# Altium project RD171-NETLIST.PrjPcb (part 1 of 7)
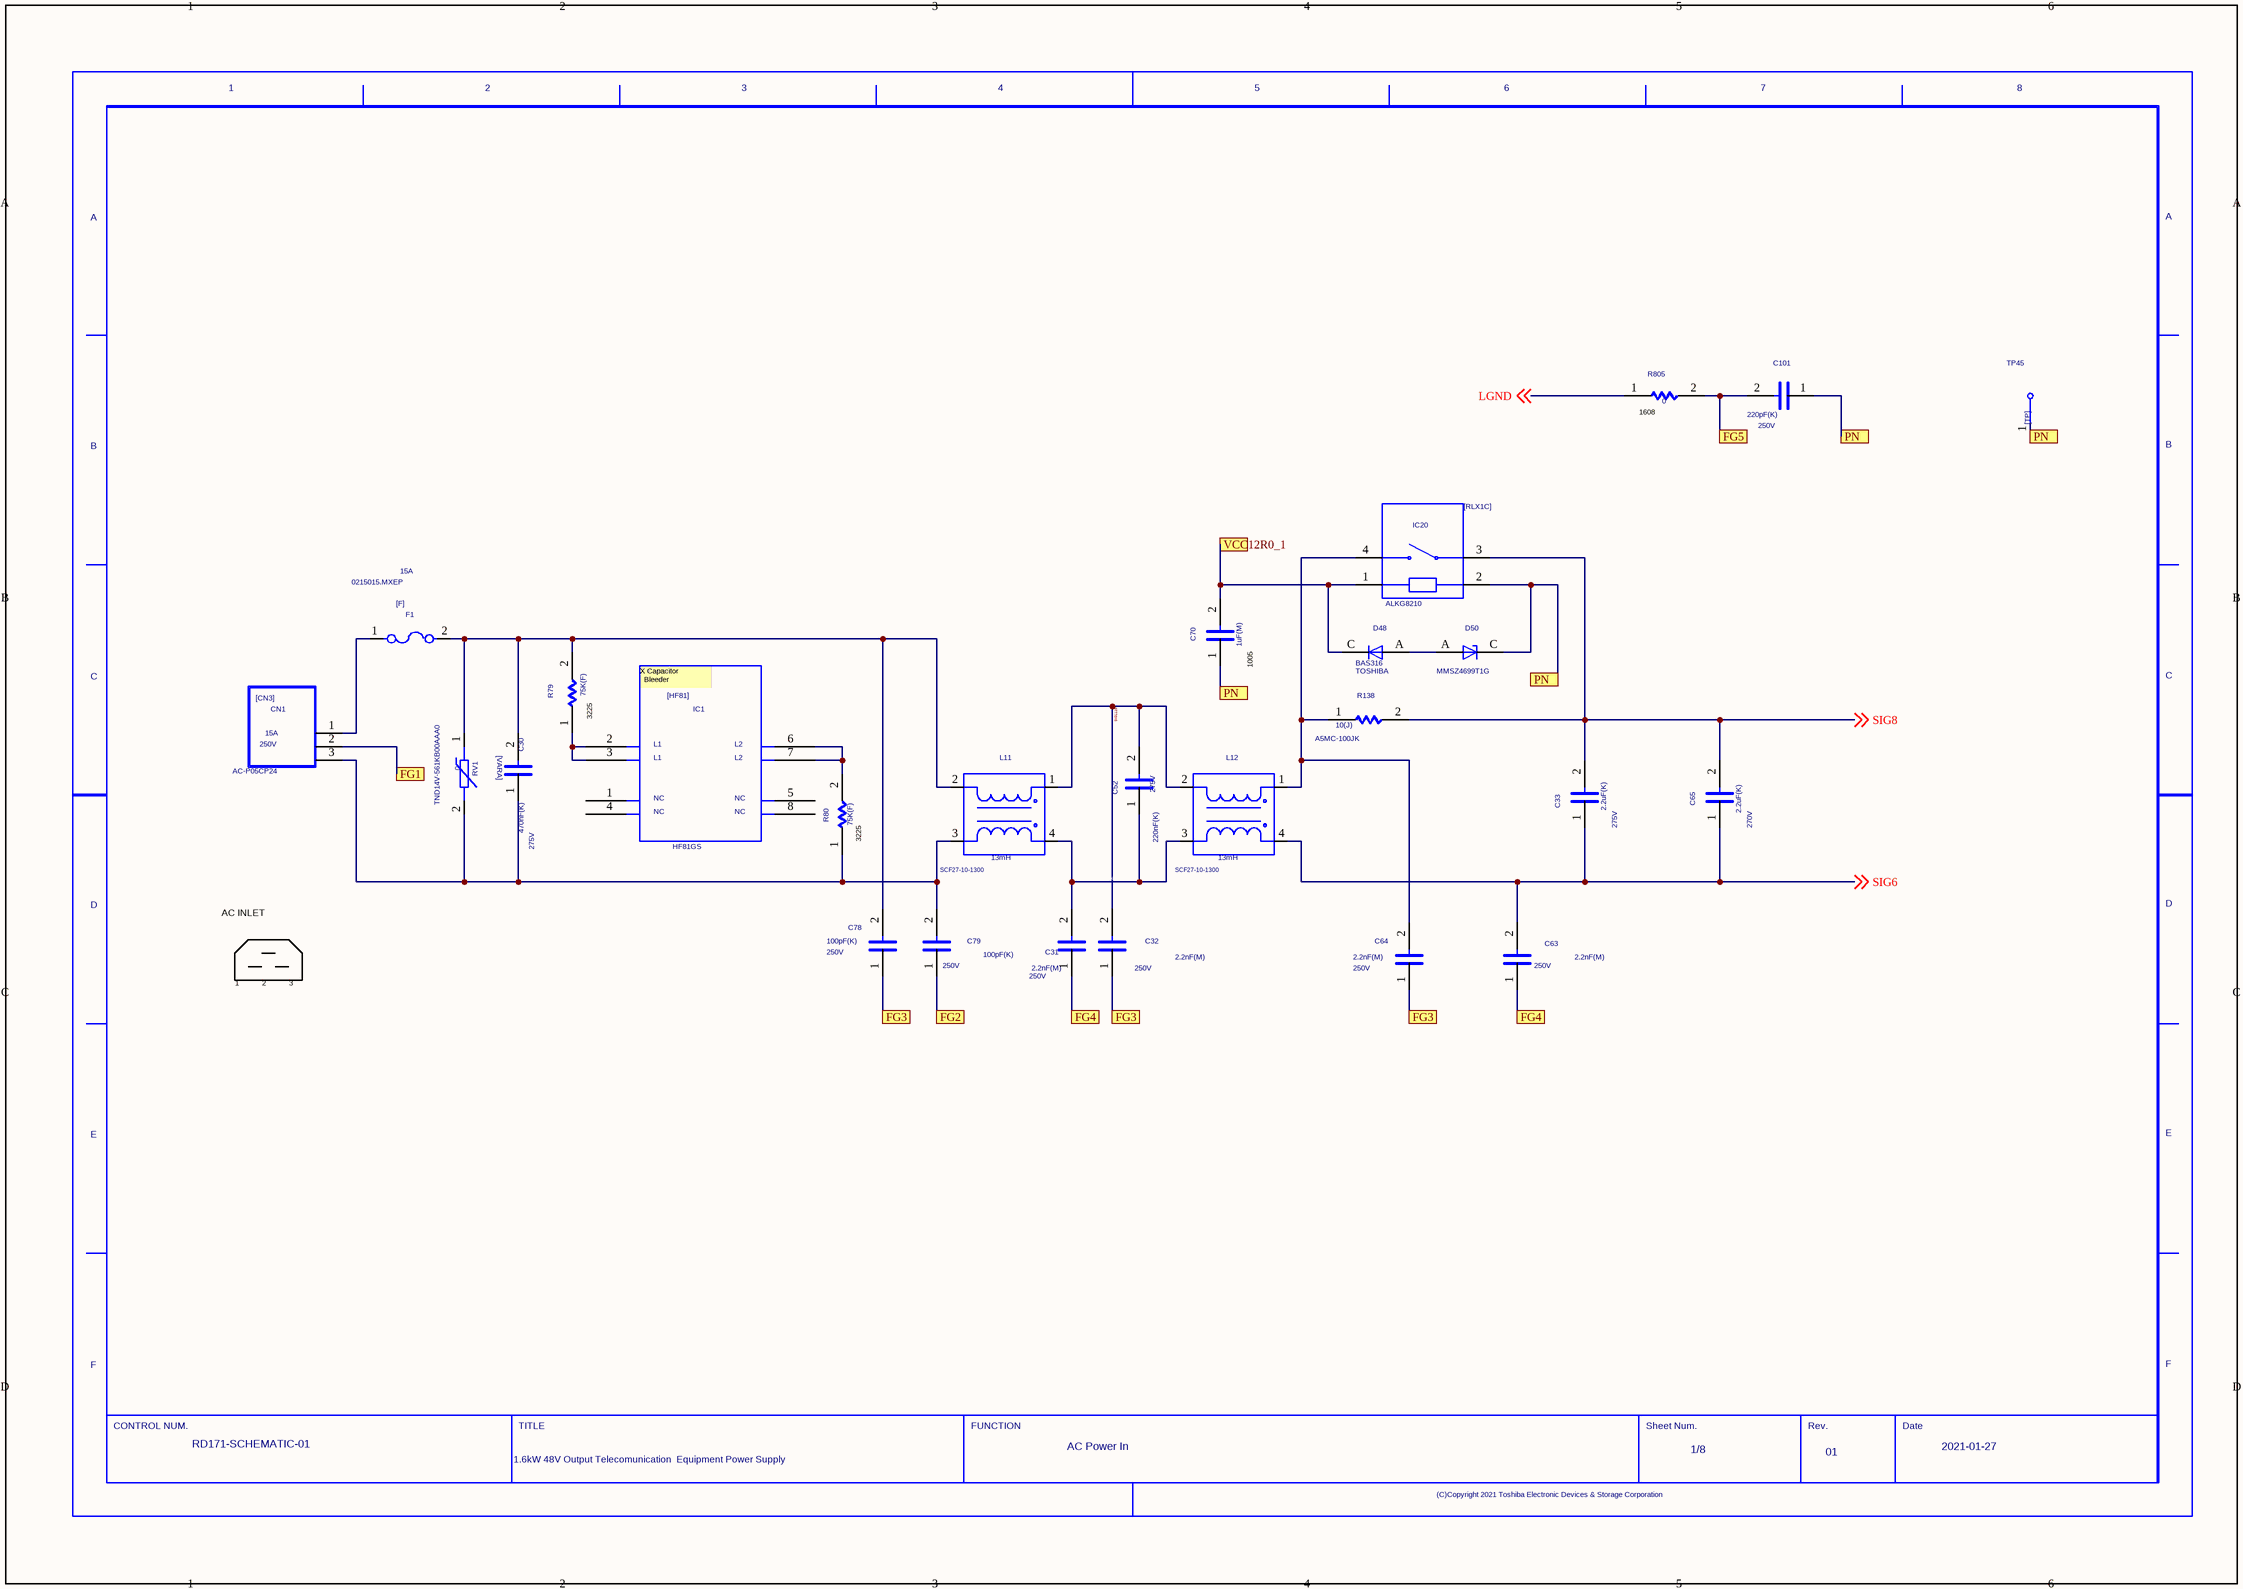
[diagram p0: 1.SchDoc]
8 sheets, 474 parts. Net scope: flat (ports and power ports of the same name join across sheets).
Sheets:
  1.SchDoc
  2.SchDoc
  3.SchDoc
  4.SchDoc
  5.SchDoc
  6.SchDoc
  7.SchDoc
  8.SchDoc

## Sheet 1.SchDoc
size 420 x 297 mm

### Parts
(Parts that share a designator on the sheet are numbered #1, #2 ... from top to bottom, then left to right.)
C30  VAL2: 275V  VAL1: 470nF(K)  [LE474-M]  (hidden comment: 470nF)
C31  VAL2: 250V  VAL1: 2.2nF(M)  [DE2E3KY222MN3AM02F]  (hidden comment: 2.2nF)
C32  VAL2: 250V  VAL1: 2.2nF(M)  [DE2E3KY222MN3AM02F]  (hidden comment: 2.2nF)
C33  VAL2: 275V  VAL1: 2.2uF(K)  [890324026034CS]  (hidden comment: 2.2uF)
C52  VAL2: 275V  VAL1: 220nF(K)  [LE224-M]  (hidden comment: 220nF)
C63  VAL2: 250V  VAL1: 2.2nF(M)  [DE2E3KY222MN3AM02F]  (hidden comment: 2.2nF)
C64  VAL2: 250V  VAL1: 2.2nF(M)  [DE2E3KY222MN3AM02F]  (hidden comment: 2.2nF)
C65  VAL2: 270V  VAL1: 2.2uF(K)  [890324026034CS]  (hidden comment: 2.2uF)
C70  VAL1: 1uF(M)  (hidden comment: 1uF)
C78  VAL2: 250V  VAL1: 100pF(K)  [DE2B3KY101KA3BM02F]  (hidden comment: 100pF)
C79  VAL2: 250V  VAL1: 100pF(K)  [DE2B3KY101KA3BM02F]  (hidden comment: 100pF)
C101  VAL2: 250V  VAL1: 220pF(K)  [DE2B3KY221KA3BM02F]  (hidden comment: 220pF)
CN1  VAL2: 250V  [AC-P05CP24]  (hidden comment: 15A)
D48  USERCOMPTEXT3: TOSHIBA  [BAS316]  (hidden comment: D48)
D50  D50  [MMSZ4699T1G]  (value not drawn)
F1  VAL1: 15A  [0215015.MXEP]  (hidden comment: 15 A)
IC1  IC1  [HF81GS]  (value not drawn)
IC20  IC20  [ALKG8210]  (value not drawn)
L11  13mH  [SCF27-10-1300]
L12  13mH  [SCF27-10-1300]
R79  VAL1: 75K(F)  (hidden comment: 75k)
R80  VAL1: 75K(F)  (hidden comment: 75k)
R138  VAL1: 10(J)  [A5MC-100JK]  (hidden comment: 10_2.1W- FUSE)
R805  0
RV1  560V  [TND14V-561KB00AAA0]  (value not drawn)
TP45  TP45  [LC-22-S-WHITE]  (value not drawn)
U?#1  DATE: 2021-01-27  REVISION: 01  SHEETNUMBER: 1/8  FUNCTION: AC Power In  TITLE: 1.6kW 48V Output Telecomunication / Equipment Power Supply  DRAWINGNUMBER: RD171-SCHEMATIC-01  (hidden comment: WAKU_DEF100)

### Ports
FG1, FG2, FG3, FG4, FG5, PN, VCC12R0_1

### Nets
LGND: R805.1 ; off-sheet LGND
SIG1: C30.2 C78.2 F1.2 L11.2 R79.2 RV1.1
SIG2: C30.1 C79.2 CN1.3 L11.3 R80.1 RV1.2
SIG6: C33.1 C63.2 C65.1 L12.4 ; off-sheet SIG6
SIG8: C33.2 C65.2 IC20.3 R138.2 ; off-sheet SIG8
SIG9: IC1.2 IC1.3 R79.1
SIG10: IC1.6 IC1.7 R80.2
SIG193: CN1.1 F1.1
SIG200: C31.2 C52.1 L11.4 L12.3
SIG1119: C32.2 C52.2 L11.1 L12.2
SIGN275: D48.A D50.A
SIGN364: C64.2 IC20.4 L12.1 R138.1
NetC1_1: C70.1 C101.1 D50.C IC20.2 TP45.1 ; port PN
NetC31_1: C31.1 C63.1 ; port FG4
NetC32_1: C32.1 C64.1 C78.1 ; port FG3
NetC70_2: C70.2 D48.C IC20.1 ; port VCC12R0_1
NetC79_1: C79.1 ; port FG2
NetC101_2: C101.2 R805.2 ; port FG5
NetCN1_2: CN1.2 ; port FG1

Not connected (* = marked no-connect by the designer): IC1 1 4 5 8

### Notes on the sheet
- (near R805) 1608
- (near C70) 1005
- (near R79) 3225
- (near R80) 3225
- AC INLET
- 1
- 2
- 3

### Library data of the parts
C30 = C: PARTNAME: LE474-M_OK; ORIGINALSYMBOLORIGIN: (0,0); TIME: 16:40:04; UPDATEUSER: t5459927; SAVECOUNT: 1; COMPONENTNAME: C_C.Normal_package; SIZECODESMD: 3225; RATEDVOLTAGE: 100; ADSMODELNAME: s_GRM32MR72A474KA01L; CAPACITANCETOLE: K; NOMINALCAPACITA: 470n; MAKER: OKAYA; COMP: PRT_19; INSTANCENAME: INS121
C31 = C: PARTNAME: DE2E3KY222MN3AM02F_MU; ORIGINALSYMBOLORIGIN: (0,0); TIME: 16:40:04; UPDATEUSER: t5459927; SAVECOUNT: 1; QUADMODEL: CON_2.2N; FUNCTION: C_C.Normal_package; NOMINALCAPACITA: 2.2n; RATEDVOLTAGE: 250; CDMASTERCADCELG: DC0284; MAKER: MURATA; TEMPCHARACTERI2: E; SIZECODESMD: DIP; OUMEMAKER: NAE パナソニックエレクトロニックデバイス; COMP: PRT_13; ADSMODELNAME: s_ECKNTS222ME; PMPRODUCTSTYPEG: ES; FNLEADFREETHET1GT2GMCTH1: N_N_N; CAPACITANCETOLE: M; OUMECLASSIFICATION: セラミックコンデンサ; OUMEMAKERKATAMEI: ECKNTS222ME; CHIPSIZE: リードピッチ7.5mm品希望; INSTANCENAME: INS259
C32 = C: PARTNAME: DE2E3KY222MN3AM02F_MU; ORIGINALSYMBOLORIGIN: (0,0); TIME: 16:40:04; UPDATEUSER: t5459927; SAVECOUNT: 1; QUADMODEL: CON_2.2N; FUNCTION: C_C.Normal_package; NOMINALCAPACITA: 2.2n; RATEDVOLTAGE: 250; CDMASTERCADCELG: DC0284; MAKER: MURATA; TEMPCHARACTERI2: E; SIZECODESMD: DIP; OUMEMAKER: NAE パナソニックエレクトロニックデバイス; ADSCNVFLAG: ON; COMP: PRT_13; ADSMODELNAME: s_ECKNTS222ME; PMPRODUCTSTYPEG: ES; FNLEADFREETHET1GT2GMCTH1: N_N_N; CAPACITANCETOLE: M; OUMECLASSIFICATION: セラミックコンデンサ; OUMEMAKERKATAMEI: ECKNTS222ME; CHIPSIZE: リードピッチ7.5mm品希望; INSTANCENAME: INS269
C33 = C: PARTNAME: 890324026034CS_WE; ORIGINALSYMBOLORIGIN: (0,0); TIME: 16:40:04; UPDATEUSER: t5459927; SAVECOUNT: 1; COMPONENTNAME: C_C.Normal_package; FNLEADFREETHET1GT2GMCTH1: 9_N_N; SIZECODESMD: DIP; RATEDVOLTAGE: 250; OUMEMAKER: CHM 日本ケミコン; CAPACITANCETOLE: K; NOMINALCAPACITA: 2.2u; OUMECLASSIFICATION: フィルャRンデンサ; MAKER: Wurth; OUMEMAKERKATAMEI: TACB2E225K; CDMASTERCADCELG: DC0511; QUADMODEL: CON_2.2U; COMP: PRT_18; INSTANCENAME: INS309
C52 = C: PARTNAME: LE224-M_OK; ORIGINALSYMBOLORIGIN: (0,0); TIME: 16:40:04; UPDATEUSER: t5459927; SAVECOUNT: 1; COMPONENTNAME: C_C.Normal_package; FNLEADFREETHET1GT2GMCTH1: N_N_N; SIZECODESMD: DIP; RATEDVOLTAGE: 275; OUMEMAKER: NIS ニッセイ電機; CAPACITANCETOLE: M; NOMINALCAPACITA: 220n; OUMECLASSIFICATION: フィルャRンデンサ; MAKER: OKAYA; OUMEMAKERKATAMEI: R40KI322000**M; QUADMODEL: CON_220N; COMP: PRT_17; INSTANCENAME: INS279
C63 = C: PARTNAME: DE2E3KY222MN3AM02F_MU; ORIGINALSYMBOLORIGIN: (0,0); TIME: 16:40:04; UPDATEUSER: t5459927; SAVECOUNT: 1; QUADMODEL: CON_2.2N; FUNCTION: C_C.Normal_package; NOMINALCAPACITA: 2.2n; RATEDVOLTAGE: 250; CDMASTERCADCELG: SIK0018; MAKER: MURATA; TEMPCHARACTERI2: E; SIZECODESMD: DIP; OUMEMAKER: MRT 村田製作所; COMP: PRT_13; ADSMODELNAME: s_DE2E3KY222MN3AM02F; PMPRODUCTSTYPEG: PC1; FNLEADFREETHET1GT2GMCTH1: N_N_N; CAPACITANCETOLE: M; OUMECLASSIFICATION: セラミックコンデンサ; CHIPSIZE: リードピッチ7.5mm品希望; INSTANCENAME: INS289
C64 = C: PARTNAME: DE2E3KY222MN3AM02F_MU; ORIGINALSYMBOLORIGIN: (0,0); TIME: 16:40:04; UPDATEUSER: t5459927; SAVECOUNT: 1; QUADMODEL: CON_2.2N; FUNCTION: C_C.Normal_package; NOMINALCAPACITA: 2.2n; RATEDVOLTAGE: 250; CDMASTERCADCELG: SIK0018; MAKER: MURATA; TEMPCHARACTERI2: E; SIZECODESMD: DIP; OUMEMAKER: MRT 村田製作所; COMP: PRT_13; ADSMODELNAME: s_DE2E3KY222MN3AM02F; PMPRODUCTSTYPEG: PC1; FNLEADFREETHET1GT2GMCTH1: N_N_N; CAPACITANCETOLE: M; OUMECLASSIFICATION: セラミックコンデンサ; CHIPSIZE: リードピッチ7.5mm品希望; INSTANCENAME: INS299
C65 = C: PARTNAME: 890324026034CS_WE; ORIGINALSYMBOLORIGIN: (0,0); TIME: 16:40:04; UPDATEUSER: t5459927; SAVECOUNT: 1; COMPONENTNAME: C_C.Normal_package; FNLEADFREETHET1GT2GMCTH1: 9_N_N; SIZECODESMD: DIP; RATEDVOLTAGE: 250; OUMEMAKER: CHM 日本ケミコン; CAPACITANCETOLE: K; NOMINALCAPACITA: 2.2u; OUMECLASSIFICATION: フィルャRンデンサ; MAKER: Wurth; OUMEMAKERKATAMEI: TACB2E225K; CDMASTERCADCELG: DC0511; QUADMODEL: CON_2.2U; COMP: PRT_18; INSTANCENAME: INS319
C70 = C: PARTNAME: Chip1005_GS_2; ORIGINALSYMBOLORIGIN: (0,0); TIME: 16:40:04; UPDATEUSER: t5459927; SAVECOUNT: 1; QUADMODEL: CON_1U; FUNCTION: C_C.Normal_package; NOMINALCAPACITA: 1u; RATEDVOLTAGE: 25; CDMASTERCADCELG: KC0005; MAKER: TDK; TEMPCHARACTERI2: B; SIZECODESMD: 1005; OUMEMAKER: MRT 村田製作所; COMP: PRT_52; ADSMODELNAME: s_GRM155B31E105KA12D; PMPRODUCTSTYPEG: HD1; FNLEADFREETHET1GT2GMCTH1: 3_0_N; VAL3: C1005X5R1E105M050BC; VAL2: 25V; CAPACITANCETOLE: K; OUMECLASSIFICATION: セラミックコンデンサ; OUMEMAKERKATAMEI: GRM155B31E105KA12D; INSTANCENAME: INS339
C78 = C: PARTNAME: DE2B3KY101KA3BM02F_MU; ORIGINALSYMBOLORIGIN: (0,0); TIME: 16:40:04; UPDATEUSER: t5459927; SAVECOUNT: 1; QUADMODEL: CON_100P; FUNCTION: C_C.Normal_package; NOMINALCAPACITA: 100p; RATEDVOLTAGE: 250; CDMASTERCADCELG: RDK0051; MAKER: MURATA; TEMPCHARACTERI2: B; OUMEMAKER: MRT 村田製作所; COMP: PRT_29; ADSMODELNAME: s_DE1B3KX101KA4BL01; FNLEADFREETHET1GT2GMCTH1: N_N_N; CAPACITANCETOLE: K; OUMECLASSIFICATION: セラミックコンデンサ; OUMEMAKERKATAMEI: DE1B3KX101KA4BL01; CHIPSIZE: リードピッチ7.5mm品希望; INSTANCENAME: INS239
C79 = C: PARTNAME: DE2B3KY101KA3BM02F_MU; ORIGINALSYMBOLORIGIN: (0,0); TIME: 16:40:04; UPDATEUSER: t5459927; SAVECOUNT: 1; QUADMODEL: CON_100P; FUNCTION: C_C.Normal_package; NOMINALCAPACITA: 100p; RATEDVOLTAGE: 250; CDMASTERCADCELG: RDK0051; MAKER: MURATA; TEMPCHARACTERI2: B; OUMEMAKER: MRT 村田製作所; COMP: PRT_29; ADSMODELNAME: s_DE1B3KX101KA4BL01; FNLEADFREETHET1GT2GMCTH1: N_N_N; CAPACITANCETOLE: K; OUMECLASSIFICATION: セラミックコンデンサ; OUMEMAKERKATAMEI: DE1B3KX101KA4BL01; CHIPSIZE: リードピッチ7.5mm品希望; INSTANCENAME: INS249
C101 = C: PARTNAME: DE2B3KY221KA3BM02F_MU; ORIGINALSYMBOLORIGIN: (0,0); TIME: 16:40:04; UPDATEUSER: t5459927; SAVECOUNT: 1; QUADMODEL: CON_220P; FUNCTION: C_C.Normal_package; NOMINALCAPACITA: 220p; RATEDVOLTAGE: 1K; CDMASTERCADCELG: RD0002; MAKER: MURATA; TEMPCHARACTERI2: B; SIZECODESMD: DIP; OUMEMAKER: MRT 村田製作所; COMP: PRT_50; ADSMODELNAME: s_DEBB33A221KC1B; FNLEADFREETHET1GT2GMCTH1: 9_1_N; CAPACITANCETOLE: K; OUMECLASSIFICATION: セラミックコンデンサ; OUMEMAKERKATAMEI: DEBB33A221KC1B; INSTANCENAME: INS329
CN1 = CN3: PARTNAME: AC-P05CP24_ED; ORIGINALSYMBOLORIGIN: (0,0); TIME: 16:40:05; UPDATEUSER: t5459927; SAVECOUNT: 1; COMP: PRT_61; FUNCTION: CN3_CN3.Normal_package; MAKER: ECHO ELECTRIC; INSTANCENAME: INS363
D48 = D: PARTNAME: BAS316_TS_B; UPDATEUSER: t5459927; UPDATETIME: 16:40:05; SAVECOUNT: 1; SAVEAREA0: -225,-91,12804,7836; ORIGINALSYMBOLORIGIN: (0,0); FUNCTION: D_D.Normal_package; CDMASTERCADCELG: D8101D; FORWARDVOLTAGEM: 0; OUMEMAKER: IFO インフィニオンテクノロジーズ; MOUNTINGFORMSMD: SMD; COMP: PRT_26; ADSMODELNAME: s_BAS16_02W; FNLEADFREETHET1GT2GMCTH1: N_N_N; OUMECLASSIFICATION: その他ダイオード; OUMEMAKERKATAMEI: BAS16-02W; INSTANCENAME: INS163
D50 = ZD: PARTNAME: MMSZ4***T*G_OS_A; OUMEPARTTYPE: D; UPDATEUSER: t5459927; UPDATETIME: 16:40:05; SAVECOUNT: 1; SAVEAREA0: -4630,-153,17114,13055; ORIGINALSYMBOLORIGIN: (0,0); FUNCTION: ZD_ZD.Normal_package; CDMASTERCADCELG: MMK0127; MAKER: ON Semiconductor; FORWARDVOLTAGEM: 0; OUMEMAKER: ONS オンセミコンダクター; MOUNTINGFORMSMD: SMD; COMP: PRT_47; ADSMODELNAME: s_MMSZ4681T1G; FNLEADFREETHET1GT2GMCTH1: N_N_N; ZENERVOLTAGEMAX: 2.52; ZENERVOLTAGEMIN: 2.28; OUMECLASSIFICATION: 定電圧ダイオード; OUMEMAKERKATAMEI: MMSZ4681T1G; INSTANCENAME: INS153
F1 = F: PARTNAME: 02150***XEP_LF; ORIGINALSYMBOLORIGIN: (0,0); TIME: 16:40:04; UPDATEUSER: t5459927; SAVECOUNT: 1; COMP: PRT_21; RATEDINTERRUPTI: 0; FUNCTION: F_F.Normal_package; MOUNTINGFORMSMD: SMD; MAKER: Littelfuse; INSTANCENAME: INS109
IC1 = L81: PARTNAME: HF81GS_MPS; UPDATEUSER: t5459927; UPDATETIME: 16:40:04; SAVECOUNT: 1; SAVEAREA0: -25132,-33687,51942,1841; ORIGINALSYMBOLORIGIN: (0,0); COMP: PRT_45; FUNCTION: L81_L81.Normal_package; MAKER: MPS; INSTANCENAME: INS131
IC20 = RLX1C: PARTNAME: ALKG*2**_PN; SAVEAREA0: -15461,-296,40419,28727; ORIGINALSYMBOLORIGIN: (0,0); SAVECOUNT: 1; TIME: 14:49:55; UPDATEUSER: cae; UPDATETIME: 11:13:08; COMP: PRT_1; FUNCTION: RLX1C_RLX1C.Normal_package; MAKER: PANASONIC; INSTANCENAME: INS349
L11 = HM_DLWHN6702: PARTNAME: SCF27-10-1300_TN; UPDATEUSER: t5459927; UPDATETIME: 16:40:05; DEVICENAME: DLW21HN670SQ2; SAVECOUNT: 1; SAVEAREA0: -21350,-26515,41553,39372; ORIGINALSYMBOLORIGIN: (0,0); VAL2: 10A; COMPONENTNAME: HM-DLWHN6702_HM-DLWHN6702.Normal_package; MAKER: NEC TOKIN; COMP: PRT_22; INSTANCENAME: INS175
L12 = HM_DLWHN6702: PARTNAME: SCF27-10-1300_TN; UPDATEUSER: t5459927; UPDATETIME: 16:40:05; DEVICENAME: DLW21HN670SQ2; SAVECOUNT: 1; SAVEAREA0: -21350,-26515,41553,39372; ORIGINALSYMBOLORIGIN: (0,0); VAL2: 10A; COMPONENTNAME: HM-DLWHN6702_HM-DLWHN6702.Normal_package; MAKER: NEC TOKIN; COMP: PRT_22; INSTANCENAME: INS191
R79 = R: PARTNAME: Chip3225_GS_1; ORIGINALSYMBOLORIGIN: (0,0); TIME: 16:40:04; UPDATEUSER: t5459927; SAVECOUNT: 1; QUADMODEL: RES_56K; FUNCTION: R_R.Normal_package; CDMASTERCADCELG: DR903A; MAKER: PANASONIC; RESISTANCETOLER: F; SIZECODESMD: 3225; OUMEMAKER: KOA コーア; POWERRATING: 250m; MOUNTINGFORMSMD: SMD; NOMINALRESISTAN: 56K; COMP: PRT_23; ADSMODELNAME: s_RK73H2ETE563F; FNLEADFREETHET1GT2GMCTH1: N_N_N; VAL3: ERJ-14NF7502U; VAL2: 500mW,±1%; OUMECLASSIFICATION: 表面実装用固定抵抗器; OUMEMAKERKATAMEI: RK73H2ETE563F; INSTANCENAME: INS219
R80 = R: PARTNAME: Chip3225_GS_1; ORIGINALSYMBOLORIGIN: (0,0); TIME: 16:40:04; UPDATEUSER: t5459927; SAVECOUNT: 1; QUADMODEL: RES_56K; FUNCTION: R_R.Normal_package; CDMASTERCADCELG: DR903A; MAKER: PANASONIC; RESISTANCETOLER: F; SIZECODESMD: 3225; OUMEMAKER: KOA コーア; POWERRATING: 250m; MOUNTINGFORMSMD: SMD; NOMINALRESISTAN: 56K; COMP: PRT_23; ADSMODELNAME: s_RK73H2ETE563F; FNLEADFREETHET1GT2GMCTH1: N_N_N; VAL3: ERJ-14NF7502U; VAL2: 500mW,±1%; OUMECLASSIFICATION: 表面実装用固定抵抗器; OUMEMAKERKATAMEI: RK73H2ETE563F; INSTANCENAME: INS229
R138 = R: PARTNAME: A5MC_UC; ORIGINALSYMBOLORIGIN: (0,0); TIME: 16:40:04; UPDATEUSER: t5459927; SAVECOUNT: 1; COMP: PRT_33; CHIPSIZE: 13x9xH25.5; FUNCTION: R_R.Normal_package; MAKER: TAKMAN; INSTANCENAME: INS207
R805 = R: PARTNAME: Chip1608_GS_1; ORIGINALSYMBOLORIGIN: (0,0); TIME: 16:40:04; UPDATEUSER: t5459927; SAVECOUNT: 1; QUADMODEL: RES_0; FUNCTION: R_R.Normal_package; CDMASTERCADCELG: KCK0203; MAKER: KOA; RESISTANCETOLER: X; SIZECODESMD: 1608; OUMEMAKER: KOA コーア; POWERRATING: 100m; MOUNTINGFORMSMD: SMD; COMP: PRT_8; ADSMODELNAME: s_RK73Z1JTTD; PMPRODUCTSTYPEG: DME-HD1-PC1; FNLEADFREETHET1GT2GMCTH1: 3_2_N; VAL3: RK73Z1JTTD; VAL2: 100mW; OUMECLASSIFICATION: 表面実装用固定抵抗器; INSTANCENAME: INS17025352
RV1 = VARA: PARTNAME: TND14V-561_CC; OUMEPARTTYPE: RV; UPDATEUSER: t5459927; UPDATETIME: 16:40:05; SAVECOUNT: 1; SAVEAREA0: -9950,-8554,25168,13619; ORIGINALSYMBOLORIGIN: (0,0); FUNCTION: VARA_VARA.Normal_package; RATEDVOLTAGE: 0; CDMASTERCADCELG: KC0008; MAKER: NIPPON CHEMICON; OUMEMAKER: TDK ＴＤＫ; MOUNTINGFORMSMD: SMD; COMP: PRT_37; FNLEADFREETHET1GT2GMCTH1: N_N_N; OUMECLASSIFICATION: バリスタ; OUMEMAKERKATAMEI: AVR-M1608C220KT6AB; INSTANCENAME: INS99
TP45 = TP: PARTNAME: LC-22_GS; UPDATEUSER: t5459927; UPDATETIME: 16:40:05; SAVECOUNT: 1; SAVEAREA0: -242,-92,12810,7836; ORIGINALSYMBOLORIGIN: (0,0); COMP: PRT_49; FUNCTION: TP_TP.Normal_package; MAKER: MAC8; INSTANCENAME: INS379
U?#1 = WAKU_DEF100: PLOTTIME: HH:MM; SAVEAREA0: 168739,-66042,466246,90057; TIME: 14:30:25; UPDATEUSER: t5459927; UPDATETIME: 15:16:57; SAVECOUNT: 5; OriginalSymbolOrigin: (10160,284480)

## Sheet 2.SchDoc
size 431 x 292 mm
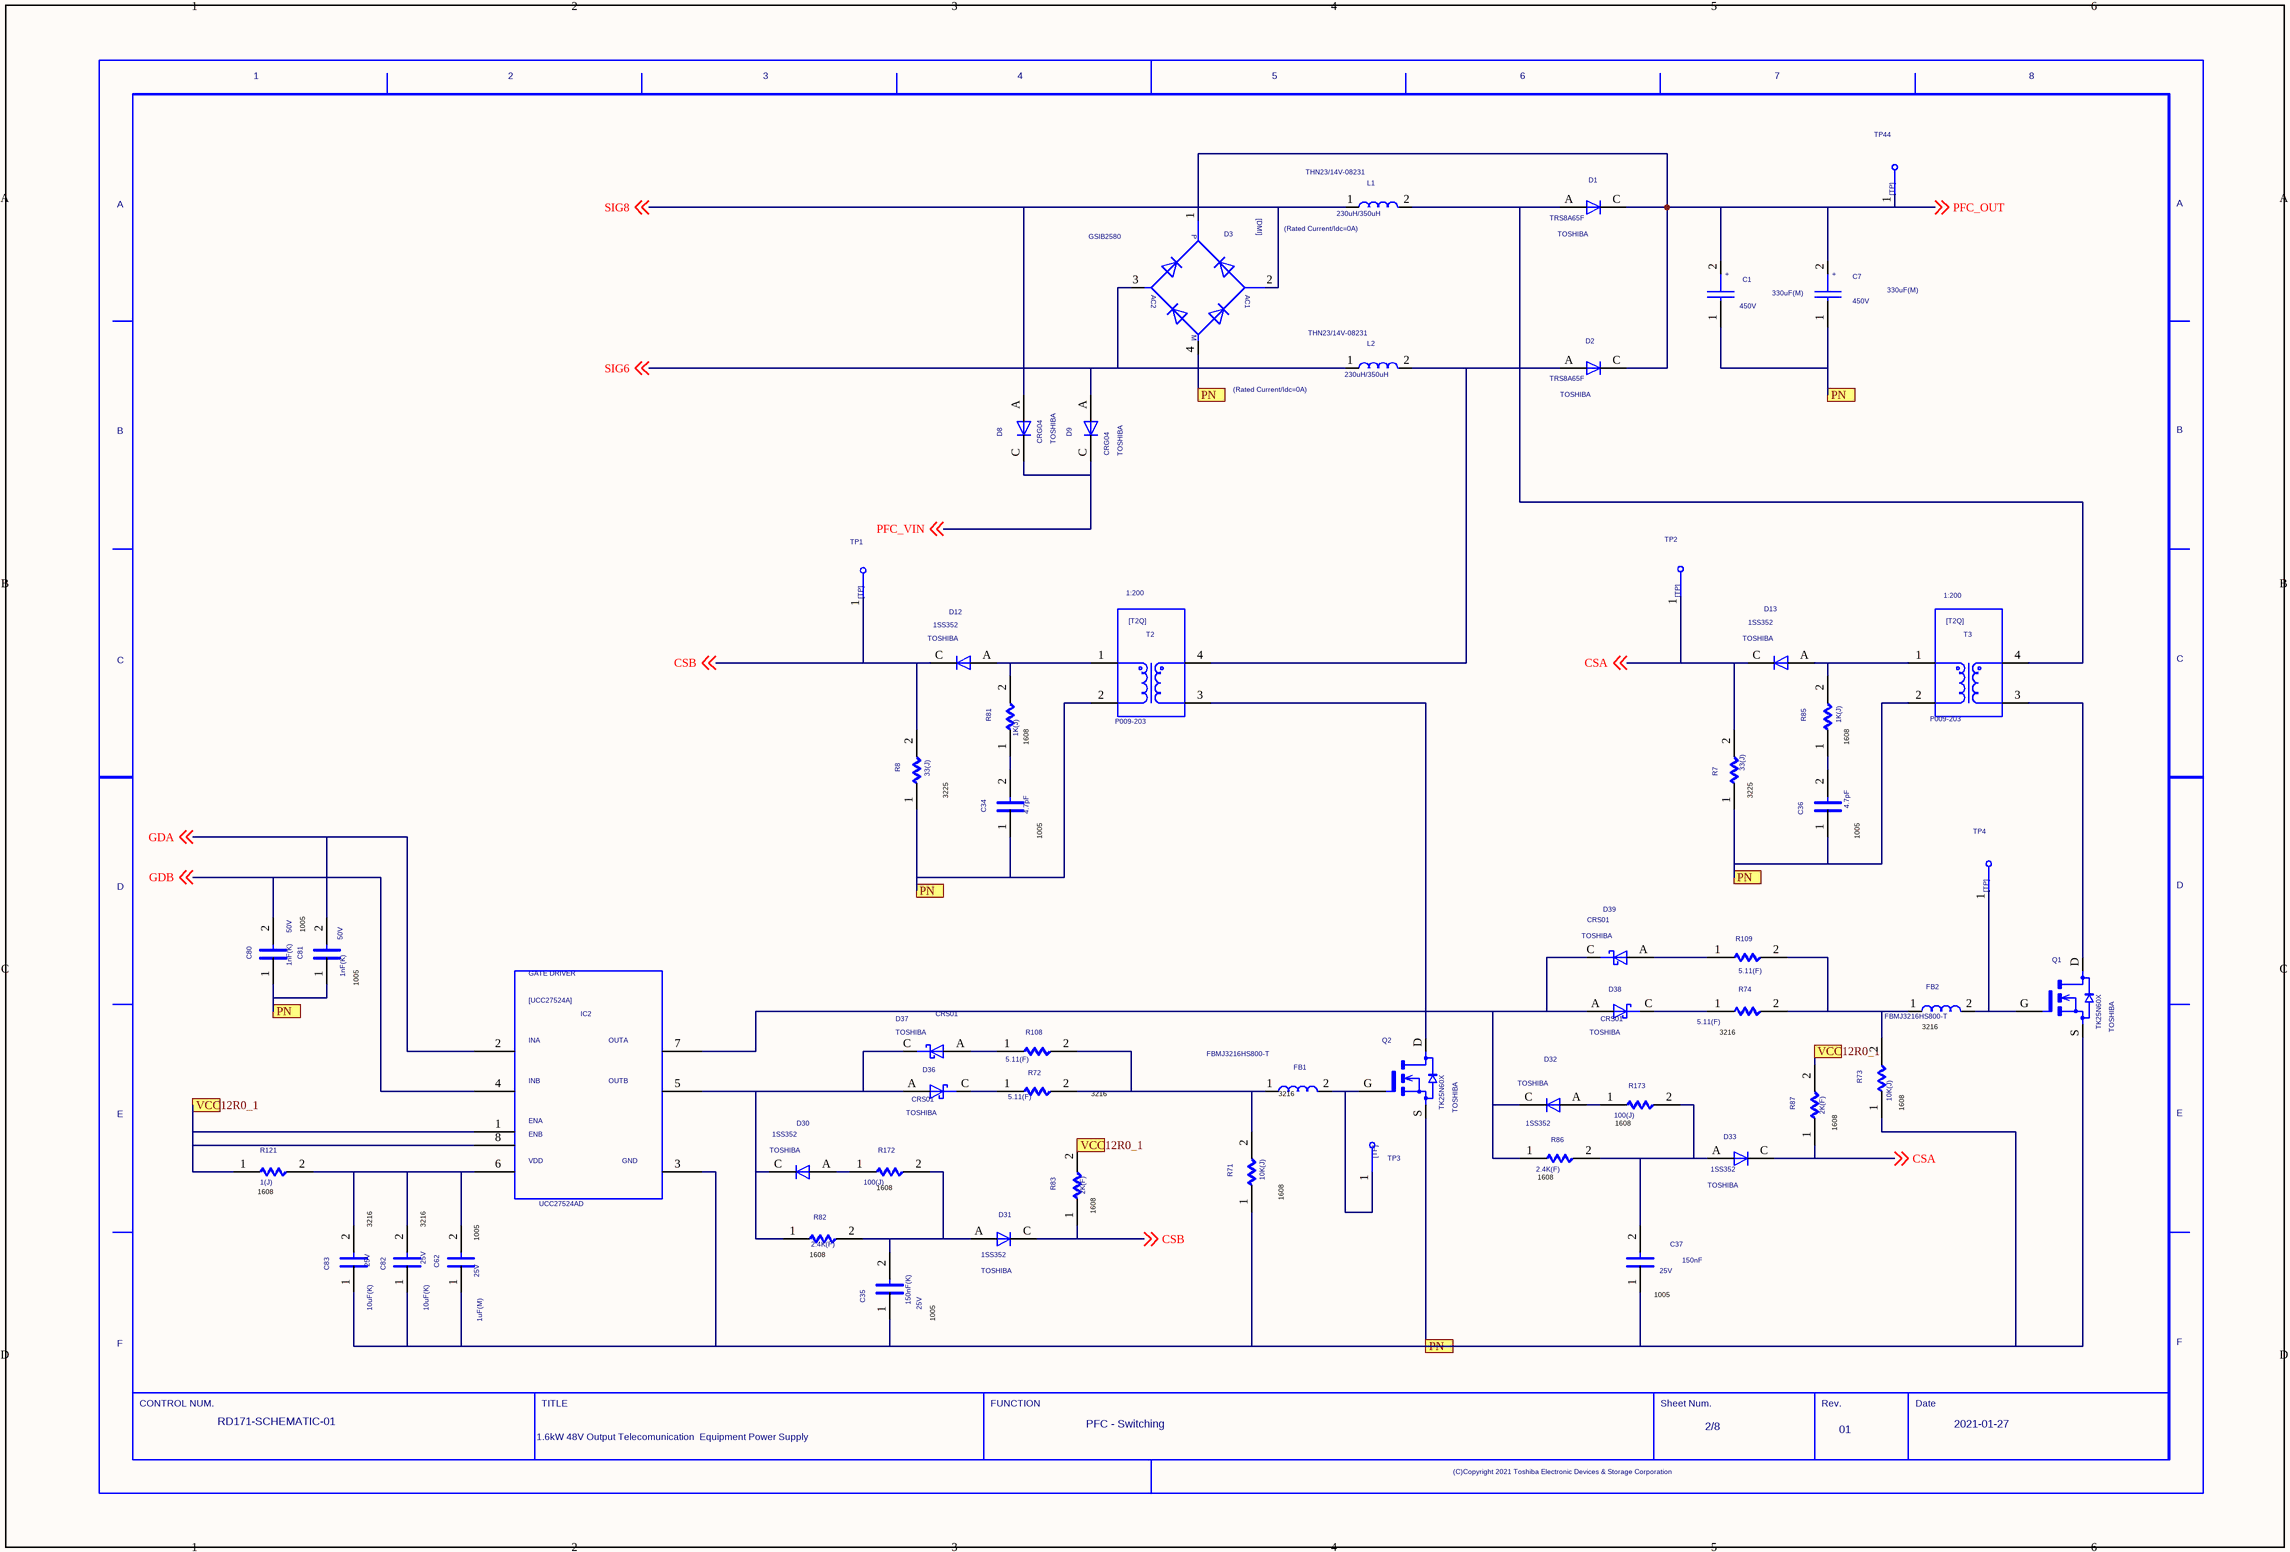
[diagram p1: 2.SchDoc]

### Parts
(Parts that share a designator on the sheet are numbered #1, #2 ... from top to bottom, then left to right.)
C1  VAL2: 450V  VAL1: 330uF(M)  [450MXK330MEFCSN30X30]  (hidden comment: 330uF)
C7  VAL2: 450V  VAL1: 330uF(M)  [450MXK330MEFCSN30X30]  (hidden comment: 330uF)
C34  4.7pF
C35  VAL2: 25V  VAL1: 150nF(K)  [C1005X5R1E154K050BC]  (hidden comment: 150nF)
C36  4.7pF
C37  VAL2: 25V  [C1005X5R1E154K050BC]  (hidden comment: 150nF)
C62  VAL2: 25V  VAL1: 1uF(M)  (hidden comment: 1uF)
C80  VAL2: 50V  VAL1: 1nF(K)  (hidden comment: 1nF)
C81  VAL2: 50V  VAL1: 1nF(K)  (hidden comment: 1nF)
C82  VAL2: 25V  VAL1: 10uF(K)  (hidden comment: 10uF)
C83  VAL2: 25V  VAL1: 10uF(K)  (hidden comment: 10uF)
D1  USERCOMPTEXT3: TOSHIBA  VAL3: TRS8A65F  [TRS8E65F]  (hidden comment: D1)
D2  USERCOMPTEXT3: TOSHIBA  VAL3: TRS8A65F  [TRS8E65F]  (hidden comment: D2)
D3  D3  [GSIB2580]  (value not drawn)
D8  USERCOMPTEXT3: TOSHIBA  [CRG04]  (hidden comment: D8)
D9  USERCOMPTEXT3: TOSHIBA  [CRG04]  (hidden comment: D9)
D12  USERCOMPTEXT3: TOSHIBA  [1SS352]  (hidden comment: D12)
D13  USERCOMPTEXT3: TOSHIBA  [1SS352]  (hidden comment: D13)
D30  USERCOMPTEXT3: TOSHIBA  [1SS352]  (hidden comment: D30)
D31  USERCOMPTEXT3: TOSHIBA  [1SS352]  (hidden comment: D31)
D32  USERCOMPTEXT3: TOSHIBA  [1SS352]  (hidden comment: D32)
D33  USERCOMPTEXT3: TOSHIBA  [1SS352]  (hidden comment: D33)
D36  USERCOMPTEXT3: TOSHIBA  [CRS01]  (hidden comment: D36)
D37  USERCOMPTEXT3: TOSHIBA  [CRS01]  (hidden comment: D37)
D38  USERCOMPTEXT3: TOSHIBA  [CRS01]  (hidden comment: D38)
D39  USERCOMPTEXT3: TOSHIBA  [CRS01]  (hidden comment: D39)
FB1  FB1  [FBMJ3216HS800-T]  (value not drawn)
FB2  FB2  [FBMJ3216HS800-T]  (value not drawn)
IC2  IC2  [UCC27524AD]  (value not drawn)
L1  VAL2: (Rated Current/Idc=0A)  VAL1: 230uH/350uH  [THN23/14V-08231]  (hidden comment: 230uH/350uH(RatedCurrent/Idc=0))
L2  VAL2: (Rated Current/Idc=0A)  VAL1: 230uH/350uH  [THN23/14V-08231]  (hidden comment: 230uH/350uH (Rated Current/Idc=0))
Q1  USERCOMPTEXT3: TOSHIBA  [TK25N60X]  (hidden comment: Q1)
Q2  USERCOMPTEXT3: TOSHIBA  [TK25N60X]  (hidden comment: Q2)
R7  VAL1: 33(J)  (hidden comment: 33)
R8  VAL1: 33(J)  (hidden comment: 33)
R71  VAL1: 10K(J)  (hidden comment: 10k)
R72  VAL1: 5.11(F)  (hidden comment: 5.11)
R73  VAL1: 10K(J)  (hidden comment: 10k)
R74  VAL1: 5.11(F)  (hidden comment: 5.11)
R81  VAL1: 1K(J)  (hidden comment: 1K)
R82  VAL1: 2.4K(F)  (hidden comment: 2.4k)
R83  VAL1: 2K(F)  (hidden comment: 2k)
R85  VAL1: 1K(J)  (hidden comment: 1K)
R86  VAL1: 2.4K(F)  (hidden comment: 2.4k)
R87  VAL1: 2K(F)  (hidden comment: 2k)
R108  VAL1: 5.11(F)  (hidden comment: 5.11)
R109  VAL1: 5.11(F)  (hidden comment: 5.11)
R121  VAL1: 1(J)  (hidden comment: 1)
R172  VAL1: 100(J)  (hidden comment: 100)
R173  VAL1: 100(J)  (hidden comment: 100)
T2  1:200  [P009-203]
T3  1:200  [P009-203]
TP1  TP1  [HK-2-S]  (value not drawn)
TP2  TP2  [HK-2-S]  (value not drawn)
TP3  TP3  [HK-2-S]  (value not drawn)
TP4  TP4  [HK-2-S]  (value not drawn)
TP44  TP44  [HK-2-S]  (value not drawn)
U?#2  DATE: 2021-01-27  REVISION: 01  SHEETNUMBER: 2/8  FUNCTION: PFC - Switching  TITLE: 1.6kW 48V Output Telecomunication / Equipment Power Supply  DRAWINGNUMBER: RD171-SCHEMATIC-01  (hidden comment: WAKU_DEF100)

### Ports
PN, VCC12R0_1

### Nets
CSA: D13.C D33.C R7.2 R87.1 TP2.1 ; off-sheet CSA
CSB: D12.C D31.C R8.2 R83.1 TP1.1 ; off-sheet CSB
GDA: C81.2 IC2.2 ; off-sheet GDA
GDB: C80.2 IC2.4 ; off-sheet GDB
PFC_OUT: C1.2 C7.2 D1.C D2.C D3.1 TP44.1 ; off-sheet PFC_OUT
PFC_VIN: D8.C D9.C ; off-sheet PFC_VIN
SIG6: D3.3 D9.A L2.1 ; off-sheet SIG6
SIG8: D3.2 D8.A L1.1 ; off-sheet SIG8
SIG11: D2.A L2.2 T2.4
SIG12: D1.A L1.2 T3.4
SIG15: D12.A R81.2 T2.1
SIG18: Q2.D T2.3
SIG20: D13.A R85.2 T3.1
SIG21: C36.2 R85.1
SIG22: Q1.D T3.3
SIG23: FB1.1 R71.2 R72.2 R108.2
SIG24: C35.2 D31.A R82.2 R172.2
SIG25: C37.2 D33.A R86.2 R173.2
SIG27: FB2.1 R73.2 R74.2 R109.2
SIG30: D32.C D38.A D39.C IC2.7 R86.1
SIG100: D36.C R72.1
SIG101: D37.A R108.1
SIG102: D30.C D36.A D37.C IC2.5 R82.1
SIG104: C62.2 C82.2 C83.2 IC2.6 R121.2
SIG105: D39.A R109.1
SIG106: D38.C R74.1
SIG1116: C34.2 R81.1
SIGN254: D30.A R172.1
SIGN255: D32.A R173.1
SIGN266: FB1.2 Q2.G TP3.1
SIGN267: FB2.2 Q1.G TP4.1
NetC1_1: C1.1 C7.1 C34.1 C35.1 C36.1 C37.1 C62.1 C80.1 C81.1 C82.1 C83.1 D3.4 IC2.3 Q1.S Q2.S R7.1 R8.1 R71.1 R73.1 T2.2 T3.2 ; port PN
NetC70_2: IC2.1 IC2.8 R83.2 R87.2 R121.1 ; port VCC12R0_1

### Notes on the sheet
- (near R81) 1608
- (near R85) 1608
- (near R8) 3225
- (near C34) 1005
- (near R7) 3225
- (near C36) 1005
- 1005
- (near C81) 1005
- (near R74) 3216
- (near FB2) 3216
- 3216
- (near FB1) 3216
- (near R73) 1608
- (near R173) 1608
- (near R87) 1608
- (near R121) 1608
- (near C62) 1005
- (near R172) 1608
- (near R83) 1608
- (near R71) 1608
- (near R86) 1608
- (near R82) 1608
- (near C37) 1005
- (near C35) 1005

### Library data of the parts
C1 = CP: PARTNAME: 450MXK330MEFCSN30X30_RB; OUMEPARTTYPE: C; UPDATEUSER: t5459927; UPDATETIME: 16:40:04; SAVECOUNT: 1; SAVEAREA0: -1450,-153,20294,13055; ORIGINALSYMBOLORIGIN: (0,0); QUADMODEL: CON_330U; FUNCTION: CP_CP.Normal_package; NOMINALCAPACITA: 330u; RATEDVOLTAGE: 450; CDMASTERCADCELG: DC213N; MAKER: RUBYCON; SIZECODESMD: DIP; OUMEMAKER: SIT ルビコン; COMP: PRT_4; FNLEADFREETHET1GT2GMCTH1: 9_N_N; VAL3: 450MXH330; CAPACITANCETOLE: M; OUMECLASSIFICATION: アルミ電解コンデンサ; OUMEMAKERKATAMEI: 450MXC330M35X40; CHIPSIZE: D35xL30; INSTANCENAME: INS1378
C7 = CP: PARTNAME: 450MXK330MEFCSN30X30_RB; OUMEPARTTYPE: C; UPDATEUSER: t5459927; UPDATETIME: 16:40:04; SAVECOUNT: 1; SAVEAREA0: -1450,-153,20294,13055; ORIGINALSYMBOLORIGIN: (0,0); QUADMODEL: CON_330U; FUNCTION: CP_CP.Normal_package; NOMINALCAPACITA: 330u; RATEDVOLTAGE: 450; CDMASTERCADCELG: DC213N; MAKER: RUBYCON; SIZECODESMD: DIP; OUMEMAKER: SIT ルビコン; COMP: PRT_4; FNLEADFREETHET1GT2GMCTH1: 9_N_N; VAL3: 450MXH330; CAPACITANCETOLE: M; OUMECLASSIFICATION: アルミ電解コンデンサ; OUMEMAKERKATAMEI: 450MXC330M35X40; CHIPSIZE: D35xL30; INSTANCENAME: INS1388
C34 = C: PARTNAME: Chip1005_GS_2; ORIGINALSYMBOLORIGIN: (0,0); TIME: 16:40:04; UPDATEUSER: t5459927; SAVECOUNT: 1; QUADMODEL: CON_4.7P; FUNCTION: C_C.Normal_package; NOMINALCAPACITA: 4.7p; RATEDVOLTAGE: 50; CDMASTERCADCELG: KC0005; MAKER: MURATA; TEMPCHARACTERI2: CH; SIZECODESMD: 1005; OUMEMAKER: MRT 村田製作所; COMP: PRT_52; ADSMODELNAME: s_GRM1552C1H4R7CA01D; PMPRODUCTSTYPEG: DME; FNLEADFREETHET1GT2GMCTH1: N_N_N; VAL3: GRM1555C1H4R7BA01D; VAL2: 50V,±0.1pF; OUMECLASSIFICATION: セラミックコンデンサ; OUMEMAKERKATAMEI: GRM1552C1H4R7CA01D; INSTANCENAME: INS1216
C35 = C: PARTNAME: Chip1005_GS_2; ORIGINALSYMBOLORIGIN: (0,0); TIME: 16:40:04; UPDATEUSER: t5459927; SAVECOUNT: 1; QUADMODEL: CON_47N; FUNCTION: C_C.Normal_package; NOMINALCAPACITA: 47n; RATEDVOLTAGE: 16; CDMASTERCADCELG: KC0005; MAKER: MURATA; TEMPCHARACTERI2: R; SIZECODESMD: 1005; OUMEMAKER: MRT 村田製作所; ADSCNVFLAG: ON; ADSCOMPONENTNAME: C_1005; COMP: PRT_52; ADSMODELNAME: s_GCM155R11C473KA01J; FNLEADFREETHET1GT2GMCTH1: N_N_N; CAPACITANCETOLE: K; OUMECLASSIFICATION: セラミックコンデンサ; OUMEMAKERKATAMEI: GCM155R11C473KA01J; INSTANCENAME: INS1256
C36 = C: PARTNAME: Chip1005_GS_2; ORIGINALSYMBOLORIGIN: (0,0); TIME: 16:40:04; UPDATEUSER: t5459927; SAVECOUNT: 1; QUADMODEL: CON_4.7P; FUNCTION: C_C.Normal_package; NOMINALCAPACITA: 4.7p; RATEDVOLTAGE: 50; CDMASTERCADCELG: KC0005; MAKER: MURATA; TEMPCHARACTERI2: CH; SIZECODESMD: 1005; OUMEMAKER: MRT 村田製作所; COMP: PRT_52; ADSMODELNAME: s_GRM1552C1H4R7CA01D; PMPRODUCTSTYPEG: DME; FNLEADFREETHET1GT2GMCTH1: N_N_N; VAL3: GRM1555C1H4R7BA01D; VAL2: 50V,±0.1pF; OUMECLASSIFICATION: セラミックコンデンサ; OUMEMAKERKATAMEI: GRM1552C1H4R7CA01D; INSTANCENAME: INS1206
C37 = C: PARTNAME: Chip1005_GS_2; ORIGINALSYMBOLORIGIN: (0,0); TIME: 16:40:04; UPDATEUSER: t5459927; SAVECOUNT: 1; QUADMODEL: CON_47N; FUNCTION: C_C.Normal_package; NOMINALCAPACITA: 47n; RATEDVOLTAGE: 16; CDMASTERCADCELG: KC0005; MAKER: MURATA; TEMPCHARACTERI2: R; SIZECODESMD: 1005; OUMEMAKER: MRT 村田製作所; COMP: PRT_52; ADSMODELNAME: s_GCM155R11C473KA01J; FNLEADFREETHET1GT2GMCTH1: N_N_N; CAPACITANCETOLE: K; OUMECLASSIFICATION: セラミックコンデンサ; OUMEMAKERKATAMEI: GCM155R11C473KA01J; INSTANCENAME: INS1246
C62 = C: PARTNAME: Chip1005_GS_2; ORIGINALSYMBOLORIGIN: (0,0); TIME: 16:40:04; UPDATEUSER: t5459927; SAVECOUNT: 1; QUADMODEL: CON_1U; FUNCTION: C_C.Normal_package; NOMINALCAPACITA: 1u; RATEDVOLTAGE: 16; CDMASTERCADCELG: KC0005; MAKER: TDK; SIZECODESMD: 1005; OUMEMAKER: TDK ＴＤＫ; COMP: PRT_52; ADSMODELNAME: s_C1005X5R1C105M050BC; FNLEADFREETHET1GT2GMCTH1: N_N_N; VAL3: C1005X5R1E105M050BC; CAPACITANCETOLE: M; OUMECLASSIFICATION: セラミックコンデンサ; OUMEMAKERKATAMEI: C1005X5R1C105M050BC; INSTANCENAME: INS1418
C80 = C: PARTNAME: Chip1005_GS_2; ORIGINALSYMBOLORIGIN: (0,0); TIME: 16:40:04; UPDATEUSER: t5459927; SAVECOUNT: 1; QUADMODEL: CON_1N; FUNCTION: C_C.Normal_package; NOMINALCAPACITA: 1n; RATEDVOLTAGE: 50; CDMASTERCADCELG: KC0005; MAKER: TDK; TEMPCHARACTERI2: B; SIZECODESMD: 1005; OUMEMAKER: TYD 太陽誘電; COMP: PRT_52; ADSMODELNAME: s_UMK105BJ102KV_F; PMPRODUCTSTYPEG: HD1-PC1; FNLEADFREETHET1GT2GMCTH1: 2_0_N; VAL3: UMK105BJ102KV-F; CAPACITANCETOLE: K; OUMECLASSIFICATION: セラミックコンデンサ; INSTANCENAME: INS1368
C81 = C: PARTNAME: Chip1005_GS_2; ORIGINALSYMBOLORIGIN: (0,0); TIME: 16:40:04; UPDATEUSER: t5459927; SAVECOUNT: 1; QUADMODEL: CON_1N; FUNCTION: C_C.Normal_package; NOMINALCAPACITA: 1n; RATEDVOLTAGE: 50; CDMASTERCADCELG: KC0005; MAKER: TDK; TEMPCHARACTERI2: B; SIZECODESMD: 1005; OUMEMAKER: TYD 太陽誘電; COMP: PRT_52; ADSMODELNAME: s_UMK105BJ102KV_F; PMPRODUCTSTYPEG: HD1-PC1; FNLEADFREETHET1GT2GMCTH1: 2_0_N; VAL3: UMK105BJ102KV-F; CAPACITANCETOLE: K; OUMECLASSIFICATION: セラミックコンデンサ; INSTANCENAME: INS1358
C82 = C: PARTNAME: Chip3216_GS_1; ORIGINALSYMBOLORIGIN: (0,0); TIME: 16:40:04; UPDATEUSER: t5459927; SAVECOUNT: 1; QUADMODEL: CON_10U; FUNCTION: C_C.Normal_package; NOMINALCAPACITA: 10u; RATEDVOLTAGE: 25; CDMASTERCADCELG: KC0014; MAKER: TAIYO YUDEN; SIZECODESMD: 3216; OUMEMAKER: TYD 太陽誘電; COMP: PRT_46; ADSMODELNAME: s_TMK316LD106KL_T; FNLEADFREETHET1GT2GMCTH1: N_N_N; VAL3: TMK316BJ106KL-T; CAPACITANCETOLE: K; OUMECLASSIFICATION: セラミックコンデンサ; OUMEMAKERKATAMEI: TMK316LD106KL-T; INSTANCENAME: INS1428
C83 = C: PARTNAME: Chip3216_GS_1; ORIGINALSYMBOLORIGIN: (0,0); TIME: 16:40:04; UPDATEUSER: t5459927; SAVECOUNT: 1; QUADMODEL: CON_10U; FUNCTION: C_C.Normal_package; NOMINALCAPACITA: 10u; RATEDVOLTAGE: 25; CDMASTERCADCELG: KC0014; MAKER: TAIYO YUDEN; SIZECODESMD: 3216; OUMEMAKER: TYD 太陽誘電; COMP: PRT_46; ADSMODELNAME: s_TMK316LD106KL_T; FNLEADFREETHET1GT2GMCTH1: N_N_N; VAL3: TMK316BJ106KL-T; CAPACITANCETOLE: K; OUMECLASSIFICATION: セラミックコンデンサ; OUMEMAKERKATAMEI: TMK316LD106KL-T; INSTANCENAME: INS1438
D1 = D: PARTNAME: TRS8A65F_TS; UPDATEUSER: t5459927; UPDATETIME: 16:40:05; SAVECOUNT: 1; SAVEAREA0: -225,-91,12804,7836; ORIGINALSYMBOLORIGIN: (0,0); FUNCTION: D_D.Normal_package; CDMASTERCADCELG: DCR071; FORWARDVOLTAGEM: 0; OUMEMAKER: ROH ロー・; MOUNTINGFORMSMD: DIP; COMP: PRT_12; ADSMODELNAME: s_1N4148; FNLEADFREETHET1GT2GMCTH1: N_N_N; OUMECLASSIFICATION: 小信号ダイオード; MAXREVERSEVOLTA: 100; OUMEMAKERKATAMEI: 1N4148; INSTANCENAME: INS964
D2 = D: PARTNAME: TRS8A65F_TS; UPDATEUSER: t5459927; UPDATETIME: 16:40:05; SAVECOUNT: 1; SAVEAREA0: -225,-91,12804,7836; ORIGINALSYMBOLORIGIN: (0,0); FUNCTION: D_D.Normal_package; CDMASTERCADCELG: DCR071; FORWARDVOLTAGEM: 0; OUMEMAKER: ROH ロー・; MOUNTINGFORMSMD: DIP; COMP: PRT_12; ADSMODELNAME: s_1N4148; FNLEADFREETHET1GT2GMCTH1: N_N_N; OUMECLASSIFICATION: 小信号ダイオード; MAXREVERSEVOLTA: 100; OUMEMAKERKATAMEI: 1N4148; INSTANCENAME: INS976
D3 = DMI: PARTNAME: GSIB2580_VS; OUMEPARTTYPE: D; UPDATEUSER: t5459927; UPDATETIME: 16:40:05; SAVECOUNT: 1; SAVEAREA0: -7762,-358,32649,26224; ORIGINALSYMBOLORIGIN: (0,0); FUNCTION: DMI_DMI.Normal_package; CDMASTERCADCELG: MMK0161; MAKER: VISHAY; FORWARDVOLTAGEM: 0; MAXAVERAGEFORWA: 800m; OUMEMAKER: SDG 新電元工業; MOUNTINGFORMSMD: SMD; COMP: PRT_53; REVERSECURRENT: 10u; ADSMODELNAME: s_D1UBA80_EMBEDED; MAXREPETITIVEPE: 800; FNLEADFREETHET1GT2GMCTH1: N_N_N; OUMECLASSIFICATION: 一般整流素子; OUMEMAKERKATAMEI: D1UBA80_EMBEDED; PEAKFORWARDVOLT: 950m; INSTANCENAME: INS1144
D8 = D: PARTNAME: CRG04_TS_A; UPDATEUSER: t5459927; UPDATETIME: 16:40:05; SAVECOUNT: 1; SAVEAREA0: -225,-91,12804,7836; ORIGINALSYMBOLORIGIN: (0,0); FUNCTION: D_D.Normal_package; CDMASTERCADCELG: MMK0167; FORWARDVOLTAGEM: 0; OUMEMAKER: TSB 東芝; MOUNTINGFORMSMD: SMD; COMP: PRT_24; REVERSECURRENT: 10u; ADSMODELNAME: s_CRG03_T5L_TEMQ_; PMPRODUCTSTYPEG: HD1; MAXREPETITIVEPE: 400; FNLEADFREETHET1GT2GMCTH1: N_N_N; OUMECLASSIFICATION: 一般整流素子; OUMEMAKERKATAMEI: CRG03(T5L,TEMQ); PEAKFORWARDVOLT: 1.1; INSTANCENAME: INS1048
D9 = D: PARTNAME: CRG04_TS_A; UPDATEUSER: t5459927; UPDATETIME: 16:40:05; SAVECOUNT: 1; SAVEAREA0: -225,-91,12804,7836; ORIGINALSYMBOLORIGIN: (0,0); FUNCTION: D_D.Normal_package; CDMASTERCADCELG: MMK0167; FORWARDVOLTAGEM: 0; OUMEMAKER: TSB 東芝; MOUNTINGFORMSMD: SMD; COMP: PRT_24; REVERSECURRENT: 10u; ADSMODELNAME: s_CRG03_T5L_TEMQ_; PMPRODUCTSTYPEG: HD1; MAXREPETITIVEPE: 400; FNLEADFREETHET1GT2GMCTH1: N_N_N; OUMECLASSIFICATION: 一般整流素子; OUMEMAKERKATAMEI: CRG03(T5L,TEMQ); PEAKFORWARDVOLT: 1.1; INSTANCENAME: INS1060
D12 = D: PARTNAME: 1SS352_TS_A; UPDATEUSER: t5459927; UPDATETIME: 16:40:05; SAVECOUNT: 1; SAVEAREA0: -225,-91,12804,7836; ORIGINALSYMBOLORIGIN: (0,0); FUNCTION: D_D.Normal_package; CDMASTERCADCELG: D81022; FORWARDVOLTAGEM: 0; OUMEMAKER: TSB 東芝; MOUNTINGFORMSMD: SMD; COMP: PRT_27; ADSMODELNAME: s_1SS352_TPH3_F_1_1E1A; FNLEADFREETHET1GT2GMCTH1: N_N_N; OUMECLASSIFICATION: 小信号ダイオード; MAXREVERSEVOLTA: 80; OUMEMAKERKATAMEI: 1SS352(TPH3,F)1-1E1A; INSTANCENAME: INS1072
D13 = D: PARTNAME: 1SS352_TS_A; UPDATEUSER: t5459927; UPDATETIME: 16:40:05; SAVECOUNT: 1; SAVEAREA0: -225,-91,12804,7836; ORIGINALSYMBOLORIGIN: (0,0); FUNCTION: D_D.Normal_package; CDMASTERCADCELG: D81022; FORWARDVOLTAGEM: 0; OUMEMAKER: TSB 東芝; MOUNTINGFORMSMD: SMD; COMP: PRT_27; ADSMODELNAME: s_1SS352_TPH3_F_1_1E1A; FNLEADFREETHET1GT2GMCTH1: N_N_N; OUMECLASSIFICATION: 小信号ダイオード; MAXREVERSEVOLTA: 80; OUMEMAKERKATAMEI: 1SS352(TPH3,F)1-1E1A; INSTANCENAME: INS1084
D30 = D: PARTNAME: 1SS352_TS_A; UPDATEUSER: t5459927; UPDATETIME: 16:40:05; SAVECOUNT: 1; SAVEAREA0: -225,-91,12804,7836; ORIGINALSYMBOLORIGIN: (0,0); FUNCTION: D_D.Normal_package; CDMASTERCADCELG: D81022; FORWARDVOLTAGEM: 0; OUMEMAKER: TSB 東芝; MOUNTINGFORMSMD: SMD; COMP: PRT_27; ADSMODELNAME: s_1SS352_TPH3_F_1_1E1A; FNLEADFREETHET1GT2GMCTH1: N_N_N; OUMECLASSIFICATION: 小信号ダイオード; MAXREVERSEVOLTA: 80; OUMEMAKERKATAMEI: 1SS352(TPH3,F)1-1E1A; INSTANCENAME: INS1096
D31 = D: PARTNAME: 1SS352_TS_A; UPDATEUSER: t5459927; UPDATETIME: 16:40:05; SAVECOUNT: 1; SAVEAREA0: -225,-91,12804,7836; ORIGINALSYMBOLORIGIN: (0,0); FUNCTION: D_D.Normal_package; CDMASTERCADCELG: D81022; FORWARDVOLTAGEM: 0; OUMEMAKER: TSB 東芝; ADSCNVFLAG: ON; MOUNTINGFORMSMD: SMD; ADSCOMPONENTNAME: D_D; COMP: PRT_27; ADSMODELNAME: s_1SS352_TPH3_F_1_1E1A; FNLEADFREETHET1GT2GMCTH1: N_N_N; OUMECLASSIFICATION: 小信号ダイオード; MAXREVERSEVOLTA: 80; OUMEMAKERKATAMEI: 1SS352(TPH3,F)1-1E1A; INSTANCENAME: INS1108
D32 = D: PARTNAME: 1SS352_TS_A; UPDATEUSER: t5459927; UPDATETIME: 16:40:05; SAVECOUNT: 1; SAVEAREA0: -225,-91,12804,7836; ORIGINALSYMBOLORIGIN: (0,0); FUNCTION: D_D.Normal_package; CDMASTERCADCELG: D81022; FORWARDVOLTAGEM: 0; OUMEMAKER: TSB 東芝; MOUNTINGFORMSMD: SMD; COMP: PRT_27; ADSMODELNAME: s_1SS352_TPH3_F_1_1E1A; FNLEADFREETHET1GT2GMCTH1: N_N_N; OUMECLASSIFICATION: 小信号ダイオード; MAXREVERSEVOLTA: 80; OUMEMAKERKATAMEI: 1SS352(TPH3,F)1-1E1A; INSTANCENAME: INS1120
D33 = D: PARTNAME: 1SS352_TS_A; UPDATEUSER: t5459927; UPDATETIME: 16:40:05; SAVECOUNT: 1; SAVEAREA0: -225,-91,12804,7836; ORIGINALSYMBOLORIGIN: (0,0); FUNCTION: D_D.Normal_package; CDMASTERCADCELG: D81022; FORWARDVOLTAGEM: 0; OUMEMAKER: TSB 東芝; MOUNTINGFORMSMD: SMD; COMP: PRT_27; ADSMODELNAME: s_1SS352_TPH3_F_1_1E1A; FNLEADFREETHET1GT2GMCTH1: N_N_N; OUMECLASSIFICATION: 小信号ダイオード; MAXREVERSEVOLTA: 80; OUMEMAKERKATAMEI: 1SS352(TPH3,F)1-1E1A; INSTANCENAME: INS1132
D36 = SBD: PARTNAME: CRS01_TS_B; OUMEPARTTYPE: D; UPDATEUSER: t5459927; UPDATETIME: 16:40:05; SAVECOUNT: 1; SAVEAREA0: -4630,-153,17114,13055; ORIGINALSYMBOLORIGIN: (0,0); FUNCTION: SBD_SBD.Normal_package; CDMASTERCADCELG: MM0042; FORWARDVOLTAGEM: 0; OUMEMAKER: TSB 東芝; MOUNTINGFORMSMD: SMD; COMP: PRT_11; REVERSECURRENT: 500u; ADSMODELNAME: s_CUS01_TE85L_Q_; PMPRODUCTSTYPEG: PC1; MAXREPETITIVEPE: 30; FNLEADFREETHET1GT2GMCTH1: 2_0_N; OUMECLASSIFICATION: 高速用整流素子/ショットキバリアダイオード; OUMEMAKERKATAMEI: CUS01(TE85L,Q); PEAKFORWARDVOLT: 370m; INSTANCENAME: INS1182
D37 = SBD: PARTNAME: CRS01_TS_B; OUMEPARTTYPE: D; UPDATEUSER: t5459927; UPDATETIME: 16:40:05; SAVECOUNT: 1; SAVEAREA0: -4630,-153,17114,13055; ORIGINALSYMBOLORIGIN: (0,0); FUNCTION: SBD_SBD.Normal_package; CDMASTERCADCELG: MM0042; FORWARDVOLTAGEM: 0; OUMEMAKER: TSB 東芝; MOUNTINGFORMSMD: SMD; COMP: PRT_11; REVERSECURRENT: 500u; ADSMODELNAME: s_CUS01_TE85L_Q_; PMPRODUCTSTYPEG: PC1; MAXREPETITIVEPE: 30; FNLEADFREETHET1GT2GMCTH1: 2_0_N; OUMECLASSIFICATION: 高速用整流素子/ショットキバリアダイオード; OUMEMAKERKATAMEI: CUS01(TE85L,Q); PEAKFORWARDVOLT: 370m; INSTANCENAME: INS1194
D38 = SBD: PARTNAME: CRS01_TS_B; OUMEPARTTYPE: D; UPDATEUSER: t5459927; UPDATETIME: 16:40:05; SAVECOUNT: 1; SAVEAREA0: -4630,-153,17114,13055; ORIGINALSYMBOLORIGIN: (0,0); FUNCTION: SBD_SBD.Normal_package; CDMASTERCADCELG: MM0042; FORWARDVOLTAGEM: 0; OUMEMAKER: TSB 東芝; MOUNTINGFORMSMD: SMD; COMP: PRT_11; REVERSECURRENT: 500u; ADSMODELNAME: s_CUS01_TE85L_Q_; PMPRODUCTSTYPEG: PC1; MAXREPETITIVEPE: 30; FNLEADFREETHET1GT2GMCTH1: 2_0_N; OUMECLASSIFICATION: 高速用整流素子/ショットキバリアダイオード; OUMEMAKERKATAMEI: CUS01(TE85L,Q); PEAKFORWARDVOLT: 370m; INSTANCENAME: INS1158
D39 = SBD: PARTNAME: CRS01_TS_B; OUMEPARTTYPE: D; UPDATEUSER: t5459927; UPDATETIME: 16:40:05; SAVECOUNT: 1; SAVEAREA0: -4630,-153,17114,13055; ORIGINALSYMBOLORIGIN: (0,0); FUNCTION: SBD_SBD.Normal_package; CDMASTERCADCELG: MM0042; FORWARDVOLTAGEM: 0; OUMEMAKER: TSB 東芝; MOUNTINGFORMSMD: SMD; COMP: PRT_11; REVERSECURRENT: 500u; ADSMODELNAME: s_CUS01_TE85L_Q_; PMPRODUCTSTYPEG: PC1; MAXREPETITIVEPE: 30; FNLEADFREETHET1GT2GMCTH1: 2_0_N; OUMECLASSIFICATION: 高速用整流素子/ショットキバリアダイオード; OUMEMAKERKATAMEI: CUS01(TE85L,Q); PEAKFORWARDVOLT: 370m; INSTANCENAME: INS1170
FB1 = L: PARTNAME: FBMH3216_TY; ORIGINALSYMBOLORIGIN: (0,0); TIME: 16:40:05; UPDATEUSER: t5459927; SAVECOUNT: 1; COMP: PRT_30; FUNCTION: L_L.Normal_package; MAKER: TAIYO YUDEN; INSTANCENAME: INS1316
FB2 = L: PARTNAME: FBMH3216_TY; ORIGINALSYMBOLORIGIN: (0,0); TIME: 16:40:05; UPDATEUSER: t5459927; SAVECOUNT: 1; COMP: PRT_30; FUNCTION: L_L.Normal_package; MAKER: TAIYO YUDEN; INSTANCENAME: INS1326
IC2 = L27524: PARTNAME: UCC27524ADR_TI; UPDATEUSER: t5459927; UPDATETIME: 16:40:04; SAVECOUNT: 1; SAVEAREA0: -37147,-44052,63643,2408; ORIGINALSYMBOLORIGIN: (0,0); COMP: PRT_63; FUNCTION: L27524_L27524.Normal_package; MAKER: TEXAS; INSTANCENAME: INS1336
L1 = L: PARTNAME: TH23/14V-08231_TP; ORIGINALSYMBOLORIGIN: (0,0); TIME: 16:40:05; UPDATEUSER: t5459927; SAVECOUNT: 1; COMPONENTNAME: L_L.Normal_package; INDUCTANCEMIN: 0; MOUNTINGFORMSMD: DIP; MAKER: TMP; NOMINALINDUCTA2: K; NOMINALINDUCTA1: 100u; COMP: PRT_41; INSTANCENAME: INS936
L2 = L: PARTNAME: TH23/14V-08231_TP; ORIGINALSYMBOLORIGIN: (0,0); TIME: 16:40:05; UPDATEUSER: t5459927; SAVECOUNT: 1; COMPONENTNAME: L_L.Normal_package; INDUCTANCEMIN: 0; MOUNTINGFORMSMD: DIP; MAKER: TMP; NOMINALINDUCTA2: K; NOMINALINDUCTA1: 100u; COMP: PRT_41; INSTANCENAME: INS950
Q1 = MFNF_3: PARTNAME: TK25N60X_TS; SAVEAREA0: -7027,-292,21786,15988; ORIGINALSYMBOLORIGIN: (0,0); SAVECOUNT: 1; TIME: 16:40:05; UPDATEUSER: t5459927; COMPONENTNAME: MFNF_3_MFNF_3; COMP: PRT_31; INSTANCENAME: INS1034
Q2 = MFNF_3: PARTNAME: TK25N60X_TS; SAVEAREA0: -7027,-292,21786,15988; ORIGINALSYMBOLORIGIN: (0,0); SAVECOUNT: 1; TIME: 16:40:05; UPDATEUSER: t5459927; COMPONENTNAME: MFNF_3_MFNF_3; COMP: PRT_31; INSTANCENAME: INS1004
R7 = R: PARTNAME: Chip3225_GS_1; ORIGINALSYMBOLORIGIN: (0,0); TIME: 16:40:04; UPDATEUSER: t5459927; SAVECOUNT: 1; COMP: PRT_23; CHIPSIZE: 3225; FUNCTION: R_R.Normal_package; VAL3: ERJ-14YJ330U; VAL2: 500mW,±5%; MAKER: PANASONIC; INSTANCENAME: INS1296
R8 = R: PARTNAME: Chip3225_GS_1; ORIGINALSYMBOLORIGIN: (0,0); TIME: 16:40:04; UPDATEUSER: t5459927; SAVECOUNT: 1; COMP: PRT_23; CHIPSIZE: 3225; FUNCTION: R_R.Normal_package; VAL3: ERJ-14YJ330U; VAL2: 500mW,±5%; MAKER: PANASONIC; INSTANCENAME: INS1306
R71 = R: PARTNAME: Chip1608_GS_1; ORIGINALSYMBOLORIGIN: (0,0); TIME: 16:40:04; UPDATEUSER: t5459927; SAVECOUNT: 1; QUADMODEL: RES_10K; FUNCTION: R_R.Normal_package; CDMASTERCADCELG: KC0133; MAKER: KOA; RESISTANCETOLER: J; SIZECODESMD: 1608; OUMEMAKER: KOA コーア; POWERRATING: 100m; MOUNTINGFORMSMD: SMD; COMP: PRT_8; ADSMODELNAME: s_RK73B1JTTD103J@@; FNLEADFREETHET1GT2GMCTH1: N_N_N; VAL3: RK73B1JTTD103J; VAL2: 100mW,±5%; OUMECLASSIFICATION: 表面実装用固定抵抗器; OUMEMAKERKATAMEI: RK73B1JTTD103J@@; INSTANCENAME: INS1478
R72 = R: PARTNAME: Chip3216_GS_1; ORIGINALSYMBOLORIGIN: (0,0); TIME: 16:40:04; UPDATEUSER: t5459927; SAVECOUNT: 1; QUADMODEL: RES_6.8; FUNCTION: R_R.Normal_package; CDMASTERCADCELG: DR901A; MAKER: BOURNS; RESISTANCETOLER: F; SIZECODESMD: 3216; OUMEMAKER: KOA コーア; POWERRATING: 125m; MOUNTINGFORMSMD: SMD; NOMINALRESISTAN: 6.8; COMP: PRT_5; ADSMODELNAME: s_RK73H2BTTD6R80F; FNLEADFREETHET1GT2GMCTH1: 3_1_N; VAL3: CRM1206-FX-5R11ELF; VAL2: 500mW,±1%; OUMECLASSIFICATION: 表面実装用固定抵抗器; OUMEMAKERKATAMEI: RK73H2BTTD6R80F; INSTANCENAME: INS1458
R73 = R: PARTNAME: Chip1608_GS_1; ORIGINALSYMBOLORIGIN: (0,0); TIME: 16:40:04; UPDATEUSER: t5459927; SAVECOUNT: 1; QUADMODEL: RES_10K; FUNCTION: R_R.Normal_package; CDMASTERCADCELG: KC0133; MAKER: KOA; RESISTANCETOLER: J; SIZECODESMD: 1608; OUMEMAKER: KOA コーア; POWERRATING: 100m; MOUNTINGFORMSMD: SMD; COMP: PRT_8; ADSMODELNAME: s_RK73B1JTTD103J@@; FNLEADFREETHET1GT2GMCTH1: N_N_N; VAL3: RK73B1JTTD103J; VAL2: 100mW,±5%; OUMECLASSIFICATION: 表面実装用固定抵抗器; OUMEMAKERKATAMEI: RK73B1JTTD103J@@; INSTANCENAME: INS1518
R74 = R: PARTNAME: Chip3216_GS_1; ORIGINALSYMBOLORIGIN: (0,0); TIME: 16:40:04; UPDATEUSER: t5459927; SAVECOUNT: 1; QUADMODEL: RES_6.8; FUNCTION: R_R.Normal_package; CDMASTERCADCELG: DR901A; MAKER: BOURNS; RESISTANCETOLER: F; SIZECODESMD: 3216; OUMEMAKER: KOA コーア; POWERRATING: 125m; MOUNTINGFORMSMD: SMD; NOMINALRESISTAN: 6.8; COMP: PRT_5; ADSMODELNAME: s_RK73H2BTTD6R80F; FNLEADFREETHET1GT2GMCTH1: 3_1_N; VAL3: CRM1206-FX-5R11ELF; VAL2: 500mW,±1%; OUMECLASSIFICATION: 表面実装用固定抵抗器; OUMEMAKERKATAMEI: RK73H2BTTD6R80F; INSTANCENAME: INS1488
R81 = R: PARTNAME: Chip1608_GS_1; ORIGINALSYMBOLORIGIN: (0,0); TIME: 16:40:04; UPDATEUSER: t5459927; SAVECOUNT: 1; QUADMODEL: RES_1K; FUNCTION: R_R.Normal_package; CDMASTERCADCELG: KCK0203; MAKER: KOA; RESISTANCETOLER: J; SIZECODESMD: 1608; OUMEMAKER: KOA コーア; POWERRATING: 100m; MOUNTINGFORMSMD: SMD; COMP: PRT_8; ADSMODELNAME: s_RK73B1JRTTD102J; PMPRODUCTSTYPEG: DME; FNLEADFREETHET1GT2GMCTH1: N_N_N; VAL3: RK73B1JTTD102J; VAL2: 125mW,±5%; OUMECLASSIFICATION: 表面実装用固定抵抗器; OUMEMAKERKATAMEI: RK73B1JRTTD102J; INSTANCENAME: INS1398
R82 = R: PARTNAME: Chip1608_GS_1; ORIGINALSYMBOLORIGIN: (0,0); TIME: 16:40:04; UPDATEUSER: t5459927; SAVECOUNT: 1; QUADMODEL: RES_1.74K; FUNCTION: R_R.Normal_package; CDMASTERCADCELG: KC0008; MAKER: PANASONIC; RESISTANCETOLER: F; SIZECODESMD: 1608; OUMEMAKER: KOA コーア; POWERRATING: 63m; MOUNTINGFORMSMD: SMD; NOMINALRESISTAN: 1.74K; COMP: PRT_8; ADSMODELNAME: s_RK73H1JTD1741F; FNLEADFREETHET1GT2GMCTH1: N_N_N; VAL3: ERJ-3EKF1781V; VAL2: 100mW,±1%; OUMECLASSIFICATION: 表面実装用固定抵抗器; OUMEMAKERKATAMEI: RK73H1JTD1741F; INSTANCENAME: INS1236
R83 = R: PARTNAME: Chip1608_GS_1; ORIGINALSYMBOLORIGIN: (0,0); TIME: 16:40:04; UPDATEUSER: t5459927; SAVECOUNT: 1; QUADMODEL: RES_3.6K; FUNCTION: R_R.Normal_package; CDMASTERCADCELG: DR802R; MAKER: PANASONIC; RESISTANCETOLER: F; SIZECODESMD: 1608; OUMEMAKER: NAE パナソニックエレクトロニックデバイス; POWERRATING: 63m; MOUNTINGFORMSMD: SMD; NOMINALRESISTAN: 3.6K; COMP: PRT_8; ADSMODELNAME: s_ERJ3GEYF362V; FNLEADFREETHET1GT2GMCTH1: 3_1_N; VAL3: ERJ-3EKF3571V; VAL2: 100mW,±1%; OUMECLASSIFICATION: 表面実装用固定抵抗器; OUMEMAKERKATAMEI: ERJ3GEYF362V; INSTANCENAME: INS1448
R85 = R: PARTNAME: Chip1608_GS_1; ORIGINALSYMBOLORIGIN: (0,0); TIME: 16:40:04; UPDATEUSER: t5459927; SAVECOUNT: 1; QUADMODEL: RES_1K; FUNCTION: R_R.Normal_package; CDMASTERCADCELG: KCK0203; MAKER: KOA; RESISTANCETOLER: J; SIZECODESMD: 1608; OUMEMAKER: KOA コーア; POWERRATING: 100m; MOUNTINGFORMSMD: SMD; COMP: PRT_8; ADSMODELNAME: s_RK73B1JRTTD102J; PMPRODUCTSTYPEG: DME; FNLEADFREETHET1GT2GMCTH1: N_N_N; VAL3: RK73B1JTTD102J; VAL2: 125mW,±5%; OUMECLASSIFICATION: 表面実装用固定抵抗器; OUMEMAKERKATAMEI: RK73B1JRTTD102J; INSTANCENAME: INS1408
R86 = R: PARTNAME: Chip1608_GS_1; ORIGINALSYMBOLORIGIN: (0,0); TIME: 16:40:04; UPDATEUSER: t5459927; SAVECOUNT: 1; QUADMODEL: RES_1.74K; FUNCTION: R_R.Normal_package; CDMASTERCADCELG: KC0008; MAKER: PANASONIC; RESISTANCETOLER: F; SIZECODESMD: 1608; OUMEMAKER: KOA コーア; ADSCNVFLAG: ON; POWERRATING: 63m; MOUNTINGFORMSMD: SMD; ADSCOMPONENTNAME: R_1608; NOMINALRESISTAN: 1.74K; COMP: PRT_8; ADSMODELNAME: s_RK73H1JTD1741F; FNLEADFREETHET1GT2GMCTH1: N_N_N; VAL3: ERJ-3EKF1781V; VAL2: 100mW,±1%; OUMECLASSIFICATION: 表面実装用固定抵抗器; OUMEMAKERKATAMEI: RK73H1JTD1741F; INSTANCENAME: INS1226
R87 = R: PARTNAME: Chip1608_GS_1; ORIGINALSYMBOLORIGIN: (0,0); TIME: 16:40:04; UPDATEUSER: t5459927; SAVECOUNT: 1; QUADMODEL: RES_3.6K; FUNCTION: R_R.Normal_package; CDMASTERCADCELG: DR802R; MAKER: PANASONIC; RESISTANCETOLER: F; SIZECODESMD: 1608; OUMEMAKER: NAE パナソニックエレクトロニックデバイス; POWERRATING: 63m; MOUNTINGFORMSMD: SMD; NOMINALRESISTAN: 3.6K; COMP: PRT_8; ADSMODELNAME: s_ERJ3GEYF362V; FNLEADFREETHET1GT2GMCTH1: 3_1_N; VAL3: ERJ-3EKF3571V; VAL2: 100mW,±1%; OUMECLASSIFICATION: 表面実装用固定抵抗器; OUMEMAKERKATAMEI: ERJ3GEYF362V; INSTANCENAME: INS1508
R108 = R: PARTNAME: Chip3216_GS_1; ORIGINALSYMBOLORIGIN: (0,0); TIME: 16:40:04; UPDATEUSER: t5459927; SAVECOUNT: 1; QUADMODEL: RES_6.8; FUNCTION: R_R.Normal_package; CDMASTERCADCELG: DR901A; MAKER: BOURNS; RESISTANCETOLER: F; SIZECODESMD: 3216; OUMEMAKER: KOA コーア; POWERRATING: 125m; MOUNTINGFORMSMD: SMD; NOMINALRESISTAN: 6.8; COMP: PRT_5; ADSMODELNAME: s_RK73H2BTTD6R80F; FNLEADFREETHET1GT2GMCTH1: 3_1_N; VAL3: CRM1206-FX-5R11ELF; VAL2: 500mW,±1%; OUMECLASSIFICATION: 表面実装用固定抵抗器; OUMEMAKERKATAMEI: RK73H2BTTD6R80F; INSTANCENAME: INS1468
R109 = R: PARTNAME: Chip3216_GS_1; ORIGINALSYMBOLORIGIN: (0,0); TIME: 16:40:04; UPDATEUSER: t5459927; SAVECOUNT: 1; QUADMODEL: RES_6.8; FUNCTION: R_R.Normal_package; CDMASTERCADCELG: DR901A; MAKER: BOURNS; RESISTANCETOLER: F; SIZECODESMD: 3216; OUMEMAKER: KOA コーア; POWERRATING: 125m; MOUNTINGFORMSMD: SMD; NOMINALRESISTAN: 6.8; COMP: PRT_5; ADSMODELNAME: s_RK73H2BTTD6R80F; FNLEADFREETHET1GT2GMCTH1: 3_1_N; VAL3: CRM1206-FX-5R11ELF; VAL2: 500mW,±1%; OUMECLASSIFICATION: 表面実装用固定抵抗器; OUMEMAKERKATAMEI: RK73H2BTTD6R80F; INSTANCENAME: INS1498
R121 = R: PARTNAME: Chip1608_GS_1; ORIGINALSYMBOLORIGIN: (0,0); TIME: 16:40:04; UPDATEUSER: t5459927; QUADMODEL: RES_1; FUNCTION: R_R.Normal_package; CDMASTERCADCELG: KC0008; MAKER: PANASONIC; RESISTANCETOLER: J; SIZECODESMD: 1608; OUMEMAKER: NAE パナソニックエレクトロニックデバイス; POWERRATING: 63m; MOUNTINGFORMSMD: SMD; COMP: PRT_8; ADSMODELNAME: s_ERJ3GEYJ1R0V; PMPRODUCTSTYPEG: PC1; FNLEADFREETHET1GT2GMCTH1: 2_1_N; VAL3: ERJ-3GEYJ1R0V; VAL2: 100mW,±5%; OUMECLASSIFICATION: 表面実装用固定抵抗器; OUMEMAKERKATAMEI: ERJ3GEYJ1R0V; INSTANCENAME: INS1266
R172 = R: PARTNAME: Chip1608_GS_1; ORIGINALSYMBOLORIGIN: (0,0); TIME: 16:40:04; UPDATEUSER: t5459927; SAVECOUNT: 1; COMP: PRT_8; CHIPSIZE: 1608; FUNCTION: R_R.Normal_package; VAL3: RK73B1JTTD101J; VAL2: 125mW,±5%; MAKER: KOA; INSTANCENAME: INS1276
R173 = R: PARTNAME: Chip1608_GS_1; ORIGINALSYMBOLORIGIN: (0,0); TIME: 16:40:04; UPDATEUSER: t5459927; SAVECOUNT: 1; COMP: PRT_8; CHIPSIZE: 1608; FUNCTION: R_R.Normal_package; VAL3: RK73B1JTTD101J; VAL2: 125mW,±5%; MAKER: KOA; INSTANCENAME: INS1286
T2 = T2Q: PARTNAME: P009-203_PO; OUMEPARTTYPE: T; ORIGINALSYMBOLORIGIN: (0,0); TIME: 16:40:05; UPDATEUSER: t5459927; SAVECOUNT: 1; INPUTVOLTAGE: 99.999K; RATEDFREQ: 0; FUNCTION: T2Q_T2Q.Normal_package; CDMASTERCADCELG: DT0334; MAKER: PONY; OUMEMAKER: TDK ＴＤＫ; MOUNTINGFORMSMD: DIP; COMP: PRT_7; ADSMODELNAME: s_CT332920S_46; FNLEADFREETHET1GT2GMCTH1: N_N_N; OUMECLASSIFICATION: 電源トランス; OUMEMAKERKATAMEI: CT332920S-46; INSTANCENAME: INS988
T3 = T2Q: PARTNAME: P009-203_PO; OUMEPARTTYPE: T; ORIGINALSYMBOLORIGIN: (0,0); TIME: 16:40:05; UPDATEUSER: t5459927; SAVECOUNT: 1; INPUTVOLTAGE: 99.999K; RATEDFREQ: 0; FUNCTION: T2Q_T2Q.Normal_package; CDMASTERCADCELG: DT0334; MAKER: PONY; OUMEMAKER: TDK ＴＤＫ; MOUNTINGFORMSMD: DIP; COMP: PRT_7; ADSMODELNAME: s_CT332920S_46; FNLEADFREETHET1GT2GMCTH1: N_N_N; OUMECLASSIFICATION: 電源トランス; OUMEMAKERKATAMEI: CT332920S-46; INSTANCENAME: INS1018
TP1 = TP: PARTNAME: HK-2_M8; UPDATEUSER: t5459927; UPDATETIME: 16:40:05; SAVECOUNT: 1; SAVEAREA0: -242,-92,12810,7836; ORIGINALSYMBOLORIGIN: (0,0); COMPONENTNAME: TP_TP.Normal_package; ID: CSB; MAKER: MAC8; COMP: PRT_44; INSTANCENAME: INS1528
TP2 = TP: PARTNAME: HK-2_M8; UPDATEUSER: t5459927; UPDATETIME: 16:40:05; SAVECOUNT: 1; SAVEAREA0: -242,-92,12810,7836; ORIGINALSYMBOLORIGIN: (0,0); COMPONENTNAME: TP_TP.Normal_package; ID: CSA; MAKER: MAC8; COMP: PRT_44; INSTANCENAME: INS1536
TP3 = TP: PARTNAME: HK-2_M8; UPDATEUSER: t5459927; UPDATETIME: 16:40:05; SAVECOUNT: 1; SAVEAREA0: -242,-92,12810,7836; ORIGINALSYMBOLORIGIN: (0,0); COMP: PRT_44; FUNCTION: TP_TP.Normal_package; MAKER: MAC8; INSTANCENAME: INS1552
TP4 = TP: PARTNAME: HK-2_M8; UPDATEUSER: t5459927; UPDATETIME: 16:40:05; SAVECOUNT: 1; SAVEAREA0: -242,-92,12810,7836; ORIGINALSYMBOLORIGIN: (0,0); COMPONENTNAME: TP_TP.Normal_package; ID: Q1-G; MAKER: MAC8; COMP: PRT_44; INSTANCENAME: INS1544
TP44 = TP: PARTNAME: HK-2_M8; UPDATEUSER: t5459927; UPDATETIME: 16:40:05; SAVECOUNT: 1; SAVEAREA0: -242,-92,12810,7836; ORIGINALSYMBOLORIGIN: (0,0); COMPONENTNAME: TP_TP.Normal_package; ID: PFC OUT; MAKER: MAC8; COMP: PRT_44; INSTANCENAME: INS1560
U?#2 = WAKU_DEF100: as U?#1 on sheet 1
